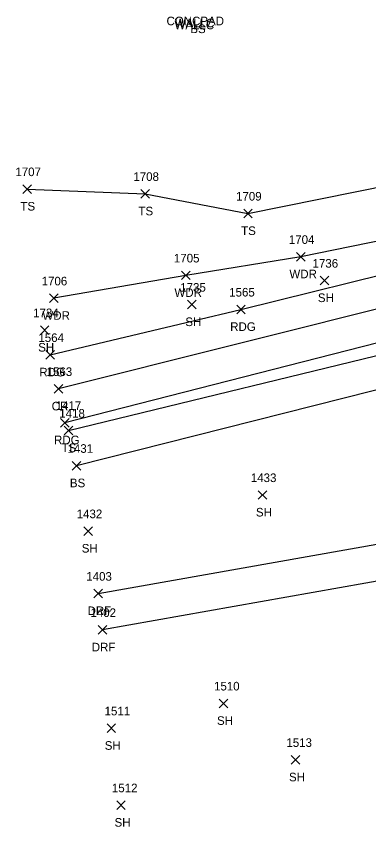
# Model space of a CAD drawing. Extents: x 1609623 to 1616187, y 756677 to 762826.
# Drawn here: x 1609795.2 to 1609877.2, y 761603.3 to 761791.7 of the extents above; entities that cross this region are included whole.
import ezdxf

# ---------------------------------------------------------------- set-up
doc = ezdxf.new("R2010")
doc.units = 0
for name, color, linetype in [('L_A', 7, 'Continuous'), ('L_I', 7, 'Continuous'), ('L_TIC', 7, 'Continuous'), ('LAWA', 7, 'Continuous'), ('LELB', 7, 'Continuous'), ('P_A', 7, 'Continuous'), ('P_I', 7, 'Continuous'), ('P_TIC', 7, 'Continuous'), ('PEU', 7, 'Continuous'), ('PRC', 7, 'Continuous'), ('R_A', 7, 'Continuous'), ('R_I', 7, 'Continuous'), ('R_TIC', 7, 'Continuous'), ('RDF', 7, 'Continuous')]:
    doc.layers.add(name, color=color, linetype=linetype)

msp = doc.modelspace()

# ---------------------------------------------------------------- linework, layer by layer
at = {"layer": 'L_TIC'}
for points in [[(1609796.77, 761750.53), (1609798.77, 761752.53)], [(1609798.77, 761750.53), (1609796.77, 761752.53)], [(1609824.21, 761749.42), (1609826.21, 761751.42)], [(1609826.21, 761749.42), (1609824.21, 761751.42)], [(1609848.09, 761744.85), (1609850.09, 761746.85)], [(1609850.09, 761744.85), (1609848.09, 761746.85)], [(1609860.36, 761734.79), (1609862.36, 761736.79)], [(1609862.36, 761734.79), (1609860.36, 761736.79)], [(1609833.63, 761730.47), (1609835.63, 761732.47)], [(1609835.63, 761730.47), (1609833.63, 761732.47)], [(1609865.85, 761729.26), (1609867.85, 761731.26)], [(1609867.85, 761729.26), (1609865.85, 761731.26)], [(1609802.94, 761725.14), (1609804.94, 761727.14)], [(1609804.94, 761725.14), (1609802.94, 761727.14)], [(1609835.03, 761723.68), (1609837.03, 761725.68)], [(1609837.03, 761723.68), (1609835.03, 761725.68)], [(1609800.82, 761717.75), (1609802.82, 761719.75)], [(1609802.82, 761717.75), (1609800.82, 761719.75)], [(1609806.34, 761694.39), (1609808.34, 761696.39)], [(1609808.34, 761694.39), (1609806.34, 761696.39)], [(1609808.24, 761686.22), (1609810.24, 761688.22)], [(1609810.24, 761686.22), (1609808.24, 761688.22)], [(1609851.44, 761679.42), (1609853.44, 761681.42)], [(1609853.44, 761679.42), (1609851.44, 761681.42)], [(1609810.95, 761671.03), (1609812.95, 761673.03)], [(1609812.95, 761671.03), (1609810.95, 761673.03)], [(1609842.4, 761630.98), (1609844.4, 761632.98)], [(1609844.4, 761630.98), (1609842.4, 761632.98)], [(1609816.31, 761625.19), (1609818.31, 761627.19)], [(1609818.31, 761625.19), (1609816.31, 761627.19)], [(1609859.14, 761617.86), (1609861.14, 761619.86)], [(1609861.14, 761617.86), (1609859.14, 761619.86)], [(1609818.57, 761607.32), (1609820.57, 761609.32)], [(1609820.57, 761607.32), (1609818.57, 761609.32)]]:
    msp.add_lwpolyline(points, dxfattribs=at)
at = {"layer": 'LAWA'}
msp.add_lwpolyline([(1610105.26, 761813.02), (1610140.61, 761813.42), (1610167.68, 761812.65), (1610195.19, 761811.82), (1610200.47, 761794.62), (1610201.65, 761767.6), (1610187.83, 761765.14), (1610147.91, 761771.28), (1610109.49, 761778.29), (1610068.49, 761778.93), (1610059.44, 761777.35), (1610050.54, 761771.19), (1610026.67, 761771.55), (1610012.41, 761775.03), (1609988.62, 761770.46), (1609964.66, 761759.68), (1609934.55, 761749.72), (1609900.52, 761743.76), (1609861.36, 761735.79), (1609834.63, 761731.47), (1609803.94, 761726.14)], dxfattribs=at)
at = {"layer": 'LELB'}
for points in [[(1609797.77, 761751.53), (1609825.21, 761750.42), (1609849.09, 761745.85), (1609882.42, 761752.62), (1609909.04, 761757.29), (1609935.48, 761757.57), (1609965.21, 761771.67), (1610002.42, 761774.81), (1610012.12, 761778.1)], [(1609807.34, 761695.39), (1609890.2, 761715.59), (1609943.65, 761729), (1609995.4, 761739.57), (1610047.96, 761745.26), (1610095.6, 761743.67), (1610138.67, 761738.82), (1610134.33, 761731.12)], [(1610134.33, 761731.12), (1610095.12, 761732.91), (1610048.19, 761735.72), (1609997.47, 761731.21), (1609946.49, 761720.77), (1609892.01, 761708.1), (1609809.24, 761687.22)]]:
    msp.add_lwpolyline(points, dxfattribs=at)
at = {"layer": 'P_TIC'}
for points in [[(1609846.46, 761722.55), (1609848.46, 761724.55)], [(1609848.46, 761722.55), (1609846.46, 761724.55)], [(1609802.09, 761711.98), (1609804.09, 761713.98)], [(1609804.09, 761711.98), (1609802.09, 761713.98)], [(1609804.01, 761704.08), (1609806.01, 761706.08)], [(1609806.01, 761704.08), (1609804.01, 761706.08)], [(1609805.51, 761696.21), (1609807.51, 761698.21)], [(1609807.51, 761696.21), (1609805.51, 761698.21)]]:
    msp.add_lwpolyline(points, dxfattribs=at)
at = {"layer": 'PEU'}
for points in [[(1609803.09, 761712.98), (1609847.46, 761723.55), (1609889.39, 761733.89), (1609939.02, 761747.01), (1609990.56, 761759.58), (1610047.77, 761766.09), (1610098.04, 761763.99), (1610151.67, 761759.1), (1610189.68, 761755.64), (1610237.76, 761754.25), (1610264.31, 761756.11)], [(1610523.28, 761673.99), (1610480.04, 761689.74), (1610439, 761706.13), (1610392.08, 761720.87), (1610334.48, 761734.06), (1610288.63, 761739.63), (1610237.75, 761740.33), (1610189.36, 761741.54), (1610151.21, 761743.29), (1610095.63, 761747.13), (1610049.42, 761749.13), (1609994.68, 761742.82), (1609943, 761732.03), (1609889.61, 761718.43), (1609806.51, 761697.21)]]:
    msp.add_lwpolyline(points, dxfattribs=at)
at = {"layer": 'PRC'}
msp.add_lwpolyline([(1610601.8, 761670.75), (1610582.15, 761672.46), (1610527.05, 761683.5), (1610483.24, 761698.98), (1610440.53, 761715.33), (1610395.01, 761729.94), (1610335.18, 761743.5), (1610288.69, 761747.54), (1610237.99, 761746.29), (1610189.61, 761747.71), (1610150.7, 761750.53), (1610096.59, 761755.33), (1610048.73, 761756.09), (1609993.41, 761750.2), (1609941.26, 761738.94), (1609887.62, 761725.82), (1609805.01, 761705.08)], dxfattribs=at)
at = {"layer": 'R_TIC'}
for points in [[(1609813.26, 761656.5), (1609815.26, 761658.5)], [(1609815.26, 761656.5), (1609813.26, 761658.5)], [(1609814.24, 761648.06), (1609816.24, 761650.06)], [(1609816.24, 761648.06), (1609814.24, 761650.06)]]:
    msp.add_lwpolyline(points, dxfattribs=at)
at = {"layer": 'RDF'}
for points in [[(1609814.26, 761657.5), (1609880.33, 761669.23), (1609931.14, 761680.03), (1609985.37, 761691.5), (1610033.07, 761700.76), (1610082.25, 761708.78), (1610121.02, 761717.5), (1610147.57, 761728), (1610151.21, 761743.29)], [(1610189.36, 761741.54), (1610170.1, 761727.36), (1610123.54, 761709.71), (1610082.66, 761698.89), (1610034.71, 761691.02), (1609986.1, 761683.34), (1609933.94, 761672.88), (1609882.6, 761661.03), (1609815.24, 761649.06)]]:
    msp.add_lwpolyline(points, dxfattribs=at)

# ---------------------------------------------------------------- texts
at = {"layer": 'L_A'}
for s, p in [('CONCPAD', (1609830.15, 761789.6)), ('WALLC', (1609832.01, 761788.66)), ('WALLC', (1609832.07, 761789.14)), ('BS', (1609835.69, 761787.78)), ('TS', (1609796.18, 761746.53)), ('TS', (1609823.62, 761745.42)), ('TS', (1609847.5, 761740.85)), ('WDR', (1609858.72, 761730.79)), ('WDR', (1609831.99, 761726.47)), ('SH', (1609865.34, 761725.26)), ('WDR', (1609801.3, 761721.14)), ('SH', (1609834.52, 761719.68)), ('SH', (1609800.31, 761713.75)), ('TS', (1609805.75, 761690.39)), ('BS', (1609807.68, 761682.22)), ('SH', (1609850.93, 761675.42)), ('SH', (1609810.44, 761667.03)), ('SH', (1609841.89, 761626.98)), ('SH', (1609815.79, 761621.19)), ('SH', (1609858.63, 761613.86)), ('SH', (1609818.06, 761603.32))]:
    msp.add_text(s, height=2, dxfattribs=at).set_placement(p)
at = {"layer": 'L_I'}
for s, p in [('1707', (1609795, 761754.53)), ('1708', (1609822.44, 761753.42)), ('1709', (1609846.31, 761748.85)), ('1704', (1609858.59, 761738.79)), ('1705', (1609831.86, 761734.47)), ('1736', (1609864.1, 761733.26)), ('1706', (1609801.11, 761729.14)), ('1735', (1609833.34, 761727.68)), ('1734', (1609799.13, 761721.75)), ('1418', (1609805.21, 761698.39)), ('1431', (1609807.12, 761690.22)), ('1433', (1609849.75, 761683.42)), ('1432', (1609809.26, 761675.03)), ('1510', (1609841.19, 761634.98)), ('1511', (1609815.75, 761629.19)), ('1513', (1609858.01, 761621.86)), ('1512', (1609817.45, 761611.32))]:
    msp.add_text(s, height=2, dxfattribs=at).set_placement(p)
at = {"layer": 'P_A'}
for s, p in [('RDG', (1609844.95, 761718.55)), ('RDG', (1609800.58, 761707.98)), ('CR', (1609803.44, 761700.08)), ('RDG', (1609804, 761692.21))]:
    msp.add_text(s, height=2, dxfattribs=at).set_placement(p)
at = {"layer": 'P_I'}
for s, p in [('1565', (1609844.72, 761726.55)), ('1564', (1609800.35, 761715.98)), ('1563', (1609802.27, 761708.08)), ('1417', (1609804.38, 761700.21))]:
    msp.add_text(s, height=2, dxfattribs=at).set_placement(p)
at = {"layer": 'R_A'}
for p in [(1609811.79, 761652.5), (1609812.77, 761644.06)]:
    msp.add_text('DRF', height=2, dxfattribs=at).set_placement(p)
at = {"layer": 'R_I'}
for s, p in [('1403', (1609811.49, 761660.5)), ('1402', (1609812.46, 761652.06))]:
    msp.add_text(s, height=2, dxfattribs=at).set_placement(p)

doc.saveas('drawing.dxf')
